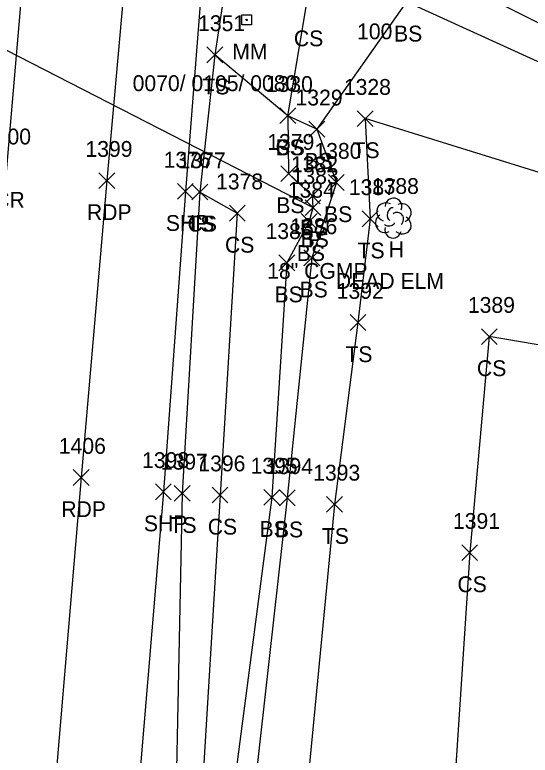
# Model space of a CAD drawing. Extents: x 1443960 to 1446865, y 610387 to 616706.
# Drawn here: x 1446594.4 to 1446659.6, y 611010.8 to 611104.4 of the extents above; entities that cross this region are included whole.
import ezdxf

# ---------------------------------------------------------------- set-up
doc = ezdxf.new("R2010")
doc.units = 0
for name, color, linetype in [('D_A', 7, 'Continuous'), ('D_C', 7, 'Continuous'), ('D_I', 7, 'Continuous'), ('D_TIC', 7, 'Continuous'), ('DCP', 7, 'Continuous'), ('L_A', 7, 'Continuous'), ('L_C', 7, 'Continuous'), ('L_I', 7, 'Continuous'), ('L_TIC', 7, 'Continuous'), ('LELB', 7, 'Continuous'), ('LTD', 7, 'Continuous'), ('P_A', 7, 'Continuous'), ('P_I', 7, 'Continuous'), ('P_TIC', 7, 'Continuous'), ('PET', 7, 'Continuous'), ('PRC', 7, 'Continuous'), ('PSP', 7, 'Continuous'), ('S_A', 7, 'Continuous'), ('S_C', 7, 'Continuous'), ('SRM', 7, 'Continuous')]:
    doc.layers.add(name, color=color, linetype=linetype)

msp = doc.modelspace()

# ---------------------------------------------------------------- linework, layer by layer
at = {"layer": 'D_TIC'}
for points in [[(1446631.152, 611078.982), (1446633.152, 611080.982)], [(1446633.152, 611078.982), (1446631.152, 611080.982)]]:
    msp.add_lwpolyline(points, dxfattribs=at)
at = {"layer": 'DCP'}
msp.add_lwpolyline([(1446632.152, 611079.982), (1446540.05, 611127.241)], dxfattribs=at)
at = {"layer": 'L_TIC'}
for points in [[(1446618.751, 611098.299), (1446620.751, 611100.299)], [(1446620.751, 611098.299), (1446618.751, 611100.299)], [(1446627.969, 611090.609), (1446629.969, 611092.609)], [(1446629.969, 611090.609), (1446627.969, 611092.609)], [(1446627.969, 611090.609), (1446629.969, 611092.609)], [(1446629.969, 611090.609), (1446627.969, 611092.609)], [(1446637.753, 611090.242), (1446639.753, 611092.242)], [(1446639.753, 611090.242), (1446637.753, 611092.242)], [(1446631.651, 611088.896), (1446633.651, 611090.896)], [(1446633.651, 611088.896), (1446631.651, 611090.896)], [(1446631.651, 611088.896), (1446633.651, 611090.896)], [(1446633.651, 611088.896), (1446631.651, 611090.896)], [(1446628.072, 611083.288), (1446630.072, 611085.288)], [(1446630.072, 611083.288), (1446628.072, 611085.288)], [(1446634.111, 611082.157), (1446636.111, 611084.157)], [(1446636.111, 611082.157), (1446634.111, 611084.157)], [(1446616.85, 611080.958), (1446618.85, 611082.958)], [(1446618.85, 611080.958), (1446616.85, 611082.958)], [(1446616.85, 611080.958), (1446618.85, 611082.958)], [(1446618.85, 611080.958), (1446616.85, 611082.958)], [(1446631.066, 611080.466), (1446633.066, 611082.466)], [(1446633.066, 611080.466), (1446631.066, 611082.466)], [(1446631.152, 611078.982), (1446633.152, 611080.982)], [(1446633.152, 611078.982), (1446631.152, 611080.982)], [(1446621.586, 611078.29), (1446623.586, 611080.29)], [(1446623.586, 611078.29), (1446621.586, 611080.29)], [(1446638.387, 611077.569), (1446640.387, 611079.569)], [(1446640.387, 611077.569), (1446638.387, 611079.569)], [(1446630.665, 611077.241), (1446632.665, 611079.241)], [(1446632.665, 611077.241), (1446630.665, 611079.241)], [(1446627.851, 611072.014), (1446629.851, 611074.014)], [(1446629.851, 611072.014), (1446627.851, 611074.014)], [(1446631.019, 611072.631), (1446633.019, 611074.631)], [(1446633.019, 611072.631), (1446631.019, 611074.631)], [(1446636.847, 611064.455), (1446638.847, 611066.455)], [(1446638.847, 611064.455), (1446636.847, 611066.455)], [(1446653.449, 611062.681), (1446655.449, 611064.681)], [(1446655.449, 611062.681), (1446653.449, 611064.681)], [(1446614.601, 611042.859), (1446616.601, 611044.859)], [(1446616.601, 611042.859), (1446614.601, 611044.859)], [(1446619.406, 611042.647), (1446621.406, 611044.647)], [(1446621.406, 611042.647), (1446619.406, 611044.647)], [(1446625.956, 611042.36), (1446627.956, 611044.36)], [(1446627.956, 611042.36), (1446625.956, 611044.36)], [(1446627.905, 611042.298), (1446629.905, 611044.298)], [(1446629.905, 611042.298), (1446627.905, 611044.298)], [(1446633.872, 611041.47), (1446635.872, 611043.47)], [(1446635.872, 611041.47), (1446633.872, 611043.47)], [(1446650.982, 611035.37), (1446652.982, 611037.37)], [(1446652.982, 611035.37), (1446650.982, 611037.37)]]:
    msp.add_lwpolyline(points, dxfattribs=at)
at = {"layer": 'LELB'}
for points in [[(1446830.278, 611016.526), (1446811.095, 611028.659), (1446776.071, 611047.215), (1446765.101, 611052.744), (1446718.129, 611075.141), (1446677.696, 611094.8), (1446645.557, 611110.935), (1446633.092, 611119.85), (1446623.055, 611121.279), (1446619.751, 611099.299), (1446617.85, 611081.958), (1446615.601, 611043.859), (1446614.767, 611002.832), (1446608.037, 610951.597), (1446605.014, 610902.953), (1446601.472, 610861.356)], [(1446628.969, 611091.609), (1446631.3, 611105.381), (1446633.964, 611114.769)], [(1446829.253, 611014.381), (1446810.485, 611025.973), (1446776.258, 611044.05), (1446764.799, 611049.488), (1446716.623, 611070.841), (1446676.655, 611091.108), (1446643.968, 611105.984), (1446632.651, 611089.896), (1446628.969, 611091.609), (1446629.072, 611084.288), (1446632.066, 611081.466), (1446632.152, 611079.982), (1446631.665, 611078.241), (1446628.851, 611073.014), (1446626.956, 611043.36), (1446621.653, 611002.831), (1446619.789, 610952.718), (1446614.792, 610900.253), (1446612.135, 610862.121)], [(1446628.969, 611091.609), (1446619.751, 611099.299)], [(1446830.534, 611008.192), (1446807.849, 611021.069), (1446773.549, 611038.491), (1446762.295, 611043.608), (1446752.723, 611051.336), (1446711.654, 611062.43), (1446674.228, 611080.274), (1446638.753, 611091.242), (1446639.387, 611078.569), (1446637.847, 611065.455), (1446634.872, 611042.47), (1446630.924, 611001.384), (1446634.242, 610953.7), (1446628.665, 610898.682), (1446624.677, 610861.106)], [(1446632.651, 611089.896), (1446635.111, 611083.157), (1446632.019, 611073.631), (1446628.905, 611043.298), (1446624.294, 611002.308), (1446623.78, 610952.543), (1446617.991, 610899.693), (1446616.994, 610861.651)], [(1446617.85, 611081.958), (1446622.586, 611079.29), (1446620.406, 611043.647), (1446617.919, 611002.832), (1446614.272, 610952.436), (1446609.495, 610901.669), (1446605.876, 610862.025)], [(1446826.781, 610994.508), (1446805.325, 611011.947), (1446772.112, 611030.778), (1446756.486, 611034.303), (1446751.931, 611036.391), (1446704.526, 611051.583), (1446668.039, 611061.388), (1446654.449, 611063.681), (1446651.982, 611036.37), (1446649.419, 610997.325), (1446649.965, 610954.254), (1446649.354, 610895.508), (1446645.029, 610860.5)]]:
    msp.add_lwpolyline(points, dxfattribs=at)
at = {"layer": 'LTD'}
msp.add_line((1446642.293, 611078.714), (1446642.293, 611078.714), dxfattribs=at)
msp.add_line((1446642.293, 611078.714), (1446642.293, 611078.714), dxfattribs=at)
msp.add_arc((1446642.34, 611080.148), 1.047, 335.52715, 180.95627, dxfattribs=at)
for centre, major_axis, ratio, start_param, end_param in [((1446641.501, 611079.381), (1.21, -0.512), 0.895232, 1.570796, 4.712389), ((1446643.335, 611079.298), (-1.141, -0.483), 0.949671, 1.570796, 4.712389), ((1446642.085, 611079.172), (-0.208, -0.792), 0.645439, 3.141593, 6.283185), ((1446641.21, 611078.005), (0.584, -1.042), 0.959034, 3.141593, 6.283185), ((1446642.793, 611078.547), (-0.5, 0.667), 0.989748, 3.141593, 6.283185), ((1446643.293, 611077.881), (-1.09, 0.792), 0.841452, 1.570796, 4.712389), ((1446641.835, 611077.964), (-0.625, -0.083), 0.423636, 0, 3.141593), ((1446642.293, 611077.214), (0.265, 1.061), 0.942809, 1.570796, 4.712389)]:
    msp.add_ellipse(centre, major_axis=major_axis, ratio=ratio, start_param=start_param, end_param=end_param, dxfattribs=at)
at = {"layer": 'P_TIC'}
for points in [[(1446605.079, 611082.403), (1446607.079, 611084.403)], [(1446607.079, 611082.403), (1446605.079, 611084.403)], [(1446615.011, 611081.042), (1446617.011, 611083.042)], [(1446617.011, 611081.042), (1446615.011, 611083.042)], [(1446601.837, 611044.861), (1446603.837, 611046.861)], [(1446603.837, 611044.861), (1446601.837, 611046.861)], [(1446612.23, 611043.063), (1446614.23, 611045.063)], [(1446614.23, 611043.063), (1446612.23, 611045.063)]]:
    msp.add_lwpolyline(points, dxfattribs=at)
at = {"layer": 'PET'}
msp.add_lwpolyline([(1446610.706, 611136.75), (1446609.781, 611124.94), (1446606.079, 611083.403), (1446602.837, 611045.861), (1446594.91, 610952.221), (1446591.246, 610905.913), (1446588.265, 610860.887), (1446582.86, 610791.011), (1446578.03, 610732.6), (1446571.547, 610656.072), (1446565.598, 610584.231)], dxfattribs=at)
at = {"layer": 'PRC'}
msp.add_lwpolyline([(1446598.395, 611142.939), (1446597.487, 611132.619), (1446593.403, 611084.973), (1446589.915, 611047.691), (1446585, 610993.715), (1446580.73, 610956.896), (1446575.284, 610909.202), (1446570.191, 610861.522)], dxfattribs=at)
at = {"layer": 'PSP'}
msp.add_lwpolyline([(1446619.037, 611132.417), (1446618.926, 611131.582), (1446619.275, 611123.52), (1446616.011, 611082.042), (1446613.23, 611044.063), (1446609.789, 611002.89), (1446606.094, 610951.914), (1446601.783, 610903.978), (1446599.174, 610861.23), (1446593.055, 610789.594), (1446588.389, 610733.328), (1446581.302, 610654.531), (1446575.408, 610584.215)], dxfattribs=at)
at = {"layer": 'SRM'}
msp.add_lwpolyline([(1446623.14, 611104.34), (1446624.39, 611104.34), (1446624.39, 611103.09), (1446623.14, 611103.09)], close=True, dxfattribs=at)
msp.add_circle((1446623.765, 611103.715), 0.0833, dxfattribs=at)

# ---------------------------------------------------------------- texts
at = {"layer": 'D_A'}
msp.add_text('P', height=2, dxfattribs=at).set_placement((1446631.53, 611074.982))
at = {"layer": 'D_C'}
msp.add_text('18" CGMP', height=2, dxfattribs=at).set_placement((1446626.365, 611070.982))
at = {"layer": 'D_I'}
msp.add_text('1383', height=2, dxfattribs=at).set_placement((1446629.459, 611082.982))
at = {"layer": 'L_A'}
for s, p in [('BS', (1446642.409, 611100.984)), ('CS', (1446629.741, 611100.381)), ('TS', (1446618.161, 611094.299)), ('CS', (1446627.41, 611086.609)), ('BS', (1446627.41, 611086.609)), ('TS', (1446637.163, 611086.242)), ('BS', (1446631.092, 611084.896)), ('BS', (1446631.092, 611084.896)), ('BS', (1446627.513, 611079.288)), ('BS', (1446633.552, 611078.157)), ('TS', (1446616.26, 611076.958)), ('CS', (1446616.291, 611076.958)), ('BS', (1446630.507, 611076.466)), ('BS', (1446630.593, 611074.982)), ('CS', (1446621.027, 611074.29)), ('BS', (1446630.105, 611073.241)), ('TS', (1446637.796, 611073.569)), ('H', (1446641.726, 611073.714)), ('BS', (1446630.46, 611068.631)), ('BS', (1446627.292, 611068.014)), ('TS', (1446636.256, 611060.455)), ('CS', (1446652.89, 611058.681)), ('TS', (1446614.01, 611038.859)), ('CS', (1446618.847, 611038.647)), ('BS', (1446625.397, 611038.36)), ('BS', (1446627.346, 611038.298)), ('TS', (1446633.281, 611037.47)), ('CS', (1446650.423, 611031.37))]:
    msp.add_text(s, height=2, dxfattribs=at).set_placement(p)
at = {"layer": 'L_C'}
msp.add_text('DEAD ELM', height=2, dxfattribs=at).set_placement((1446635.049, 611069.714))
at = {"layer": 'L_I'}
for s, p in [('1351', (1446617.625, 611102.299)), ('1330', (1446626.19, 611094.609)), ('1330', (1446626.19, 611094.609)), ('1328', (1446636.061, 611094.242)), ('1329', (1446629.95, 611092.896)), ('1329', (1446629.95, 611092.896)), ('1379', (1446626.372, 611087.288)), ('1380', (1446632.332, 611086.157)), ('1377', (1446615.158, 611084.958)), ('1377', (1446615.158, 611084.958)), ('1382', (1446629.373, 611084.466)), ('1378', (1446619.894, 611082.29)), ('1383', (1446629.459, 611082.982)), ('1387', (1446636.694, 611081.569)), ('1388', (1446639.6, 611081.714)), ('1384', (1446628.972, 611081.241)), ('1386', (1446629.271, 611076.631)), ('1385', (1446626.158, 611076.014)), ('1392', (1446635.154, 611068.455)), ('1389', (1446651.748, 611066.681)), ('1397', (1446612.908, 611046.859)), ('1396', (1446617.658, 611046.647)), ('1395', (1446624.263, 611046.36)), ('1394', (1446626.212, 611046.298)), ('1393', (1446632.179, 611045.47)), ('1391', (1446649.857, 611039.37))]:
    msp.add_text(s, height=2, dxfattribs=at).set_placement(p)
at = {"layer": 'P_A'}
for s, p in [('CR', (1446591.836, 611079.973)), ('RDP', (1446603.567, 611078.403)), ('SHP', (1446613.546, 611077.042)), ('RDP', (1446600.325, 611040.861)), ('SHP', (1446610.766, 611039.063))]:
    msp.add_text(s, height=2, dxfattribs=at).set_placement(p)
at = {"layer": 'P_I'}
for s, p in [('1400', (1446590.545, 611087.973)), ('1399', (1446603.378, 611086.403)), ('1376', (1446613.263, 611085.042)), ('1406', (1446600.01, 611048.861)), ('1398', (1446610.538, 611047.063))]:
    msp.add_text(s, height=2, dxfattribs=at).set_placement(p)
at = {"layer": 'S_A'}
msp.add_text('MM', height=2, dxfattribs=at).set_placement((1446621.954, 611098.715))
at = {"layer": 'S_C'}
for s, p in [('100', (1446637.733, 611101.268)), ('0070/ 0105/ 0080', (1446609.348, 611094.715))]:
    msp.add_text(s, height=2, dxfattribs=at).set_placement(p)

doc.saveas('drawing.dxf')
